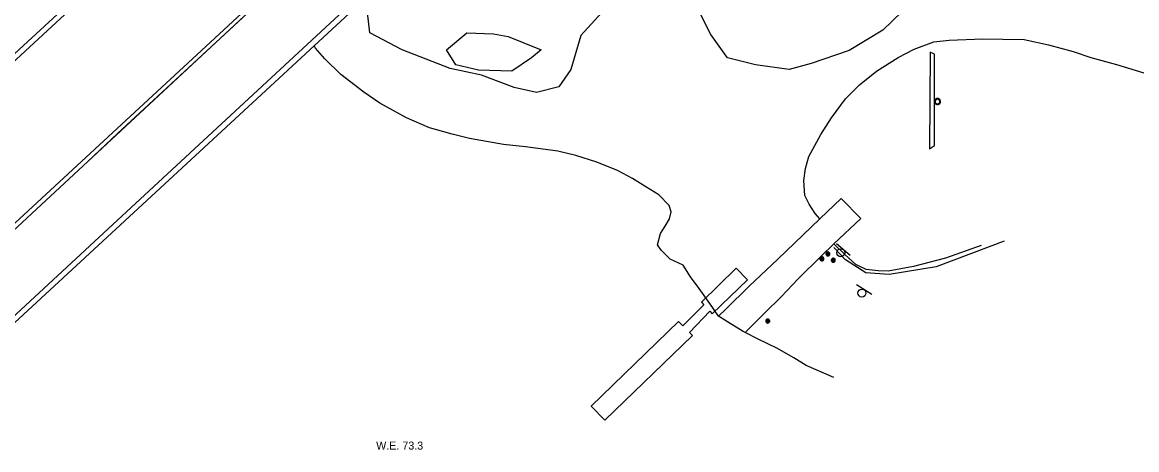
# Model space of a CAD drawing. Extents: x 2161152 to 2175754, y 602179 to 617749.
# Drawn here: x 2171946 to 2172503, y 613312 to 613525 of the extents above; entities that cross this region are included whole.
import ezdxf

# ---------------------------------------------------------------- set-up
doc = ezdxf.new("R2010")
doc.units = 0
for name, color, linetype in [('RD_EX_BldgApp_Deck', 7, 'Continuous'), ('RD_EX_BldgApp_Post', 7, 'Continuous'), ('RD_EX_BldgApp_Sign', 7, 'Continuous'), ('RD_EX_Bridge', 7, 'Continuous'), ('RD_EX_Driveway_Dirt', 7, 'Continuous'), ('RD_EX_Fence_ChLk', 7, 'Continuous'), ('RD_EX_GuardRail', 7, 'Continuous'), ('RD_EX_H2O', 7, 'Continuous'), ('RD_EX_H2O_txCode', 7, 'Continuous'), ('RD_EX_Parking_Conc', 7, 'Continuous'), ('RD_EX_VEG', 7, 'Continuous')]:
    doc.layers.add(name, color=color, linetype=linetype)

msp = doc.modelspace()

# ---------------------------------------------------------------- linework, layer by layer
at = {"layer": 'RD_EX_BldgApp_Deck'}
msp.add_lwpolyline([(2172303.05, 613402.44), (2172285.83, 613385.47), (2172286.98, 613384.23), (2172276.44, 613373.61), (2172274.25, 613375.81), (2172230.7, 613333.61), (2172237.52, 613326.58), (2172281.34, 613368.78), (2172279.79, 613370.3), (2172289.93, 613380.93), (2172291.15, 613379.63), (2172308.71, 613396.66), (2172303.05, 613402.44)], dxfattribs=at)
at = {"layer": 'RD_EX_BldgApp_Post'}
for p, q in [((2172349.54, 613409), (2172348.41, 613410.13)), ((2172348.41, 613409), (2172349.54, 613410.13)), ((2172346.53, 613406.57), (2172345.4, 613407.7)), ((2172345.4, 613406.57), (2172346.53, 613407.7)), ((2172352.23, 613405.84), (2172351.09, 613406.98)), ((2172351.09, 613405.84), (2172352.23, 613406.98)), ((2172319.43, 613375.48), (2172318.3, 613376.62)), ((2172318.3, 613375.48), (2172319.43, 613376.62))]:
    msp.add_line(p, q, dxfattribs=at)
for points in [[(2172349.98, 613409.56), (2172349.96, 613409.72), (2172349.92, 613409.88), (2172349.85, 613410.04), (2172349.75, 613410.2), (2172349.61, 613410.34), (2172349.45, 613410.45), (2172349.26, 613410.52), (2172349.07, 613410.56), (2172348.89, 613410.56), (2172348.72, 613410.53), (2172348.56, 613410.48), (2172348.43, 613410.4), (2172348.3, 613410.31), (2172348.19, 613410.18), (2172348.09, 613410.03), (2172348.01, 613409.85), (2172347.98, 613409.66), (2172347.98, 613409.46), (2172348.01, 613409.27), (2172348.09, 613409.1), (2172348.19, 613408.94), (2172348.3, 613408.82), (2172348.43, 613408.72), (2172348.56, 613408.65), (2172348.72, 613408.59), (2172348.89, 613408.56), (2172349.07, 613408.57), (2172349.26, 613408.6), (2172349.45, 613408.68), (2172349.61, 613408.79), (2172349.75, 613408.93), (2172349.85, 613409.08), (2172349.92, 613409.25), (2172349.96, 613409.41), (2172349.98, 613409.56)], [(2172349.78, 613409.56), (2172349.77, 613409.69), (2172349.73, 613409.82), (2172349.68, 613409.95), (2172349.59, 613410.07), (2172349.48, 613410.18), (2172349.35, 613410.27), (2172349.21, 613410.33), (2172349.05, 613410.36), (2172348.91, 613410.36), (2172348.77, 613410.34), (2172348.65, 613410.29), (2172348.54, 613410.24), (2172348.44, 613410.16), (2172348.34, 613410.06), (2172348.26, 613409.94), (2172348.21, 613409.8), (2172348.18, 613409.64), (2172348.18, 613409.48), (2172348.21, 613409.33), (2172348.26, 613409.19), (2172348.34, 613409.07), (2172348.44, 613408.97), (2172348.54, 613408.89), (2172348.65, 613408.83), (2172348.77, 613408.79), (2172348.91, 613408.76), (2172349.05, 613408.76), (2172349.21, 613408.79), (2172349.35, 613408.86), (2172349.48, 613408.94), (2172349.59, 613409.05), (2172349.68, 613409.18), (2172349.73, 613409.31), (2172349.77, 613409.44), (2172349.78, 613409.56)], [(2172346.96, 613407.14), (2172346.95, 613407.29), (2172346.91, 613407.45), (2172346.84, 613407.62), (2172346.74, 613407.77), (2172346.6, 613407.91), (2172346.43, 613408.02), (2172346.25, 613408.1), (2172346.06, 613408.13), (2172345.88, 613408.14), (2172345.71, 613408.11), (2172345.55, 613408.05), (2172345.42, 613407.98), (2172345.29, 613407.88), (2172345.17, 613407.76), (2172345.08, 613407.6), (2172345, 613407.43), (2172344.96, 613407.24), (2172344.96, 613407.04), (2172345, 613406.85), (2172345.08, 613406.67), (2172345.17, 613406.52), (2172345.29, 613406.39), (2172345.42, 613406.3), (2172345.55, 613406.22), (2172345.71, 613406.17), (2172345.88, 613406.14), (2172346.06, 613406.14), (2172346.25, 613406.18), (2172346.43, 613406.25), (2172346.6, 613406.36), (2172346.74, 613406.5), (2172346.84, 613406.66), (2172346.91, 613406.82), (2172346.95, 613406.98), (2172346.96, 613407.14)], [(2172346.76, 613407.14), (2172346.75, 613407.26), (2172346.72, 613407.39), (2172346.67, 613407.52), (2172346.58, 613407.65), (2172346.47, 613407.76), (2172346.34, 613407.84), (2172346.19, 613407.9), (2172346.04, 613407.94), (2172345.9, 613407.94), (2172345.76, 613407.91), (2172345.63, 613407.87), (2172345.53, 613407.81), (2172345.43, 613407.73), (2172345.33, 613407.63), (2172345.25, 613407.51), (2172345.2, 613407.37), (2172345.16, 613407.22), (2172345.16, 613407.06), (2172345.2, 613406.9), (2172345.25, 613406.76), (2172345.33, 613406.64), (2172345.43, 613406.54), (2172345.53, 613406.46), (2172345.63, 613406.41), (2172345.76, 613406.36), (2172345.9, 613406.34), (2172346.04, 613406.34), (2172346.19, 613406.37), (2172346.34, 613406.43), (2172346.47, 613406.52), (2172346.58, 613406.63), (2172346.67, 613406.75), (2172346.72, 613406.88), (2172346.75, 613407.01), (2172346.76, 613407.14)], [(2172352.66, 613406.41), (2172352.65, 613406.56), (2172352.61, 613406.73), (2172352.54, 613406.89), (2172352.43, 613407.05), (2172352.3, 613407.18), (2172352.13, 613407.29), (2172351.95, 613407.37), (2172351.76, 613407.41), (2172351.58, 613407.41), (2172351.4, 613407.38), (2172351.25, 613407.32), (2172351.12, 613407.25), (2172350.99, 613407.15), (2172350.87, 613407.03), (2172350.77, 613406.88), (2172350.7, 613406.7), (2172350.66, 613406.51), (2172350.66, 613406.31), (2172350.7, 613406.12), (2172350.77, 613405.94), (2172350.87, 613405.79), (2172350.99, 613405.66), (2172351.12, 613405.57), (2172351.25, 613405.49), (2172351.4, 613405.44), (2172351.58, 613405.41), (2172351.76, 613405.41), (2172351.95, 613405.45), (2172352.13, 613405.52), (2172352.3, 613405.63), (2172352.43, 613405.77), (2172352.54, 613405.93), (2172352.61, 613406.09), (2172352.65, 613406.25), (2172352.66, 613406.41)], [(2172352.46, 613406.41), (2172352.45, 613406.53), (2172352.42, 613406.66), (2172352.36, 613406.79), (2172352.28, 613406.92), (2172352.17, 613407.03), (2172352.04, 613407.12), (2172351.89, 613407.18), (2172351.74, 613407.21), (2172351.59, 613407.21), (2172351.46, 613407.18), (2172351.33, 613407.14), (2172351.23, 613407.08), (2172351.12, 613407.01), (2172351.03, 613406.91), (2172350.95, 613406.78), (2172350.89, 613406.64), (2172350.86, 613406.49), (2172350.86, 613406.33), (2172350.89, 613406.18), (2172350.95, 613406.04), (2172351.03, 613405.91), (2172351.12, 613405.81), (2172351.23, 613405.74), (2172351.33, 613405.68), (2172351.46, 613405.63), (2172351.59, 613405.61), (2172351.74, 613405.61), (2172351.89, 613405.64), (2172352.04, 613405.7), (2172352.17, 613405.79), (2172352.28, 613405.9), (2172352.36, 613406.02), (2172352.42, 613406.16), (2172352.45, 613406.29), (2172352.46, 613406.41)], [(2172319.87, 613376.05), (2172319.86, 613376.2), (2172319.82, 613376.37), (2172319.74, 613376.53), (2172319.64, 613376.68), (2172319.5, 613376.82), (2172319.34, 613376.93), (2172319.15, 613377.01), (2172318.97, 613377.05), (2172318.78, 613377.05), (2172318.61, 613377.02), (2172318.45, 613376.96), (2172318.32, 613376.89), (2172318.19, 613376.79), (2172318.08, 613376.67), (2172317.98, 613376.52), (2172317.91, 613376.34), (2172317.87, 613376.15), (2172317.87, 613375.95), (2172317.91, 613375.76), (2172317.98, 613375.58), (2172318.08, 613375.43), (2172318.19, 613375.3), (2172318.32, 613375.21), (2172318.45, 613375.13), (2172318.61, 613375.08), (2172318.78, 613375.05), (2172318.97, 613375.05), (2172319.15, 613375.09), (2172319.34, 613375.16), (2172319.5, 613375.27), (2172319.64, 613375.41), (2172319.74, 613375.57), (2172319.82, 613375.73), (2172319.86, 613375.89), (2172319.87, 613376.05)], [(2172319.67, 613376.05), (2172319.66, 613376.17), (2172319.63, 613376.3), (2172319.57, 613376.43), (2172319.48, 613376.56), (2172319.37, 613376.67), (2172319.24, 613376.76), (2172319.1, 613376.82), (2172318.95, 613376.85), (2172318.8, 613376.85), (2172318.66, 613376.82), (2172318.54, 613376.78), (2172318.43, 613376.72), (2172318.33, 613376.64), (2172318.23, 613376.54), (2172318.16, 613376.42), (2172318.1, 613376.28), (2172318.07, 613376.13), (2172318.07, 613375.97), (2172318.1, 613375.82), (2172318.16, 613375.67), (2172318.23, 613375.55), (2172318.33, 613375.45), (2172318.43, 613375.37), (2172318.54, 613375.32), (2172318.66, 613375.27), (2172318.8, 613375.25), (2172318.95, 613375.25), (2172319.1, 613375.28), (2172319.24, 613375.34), (2172319.37, 613375.43), (2172319.48, 613375.54), (2172319.57, 613375.66), (2172319.63, 613375.79), (2172319.66, 613375.92), (2172319.67, 613376.05)]]:
    msp.add_lwpolyline(points, dxfattribs=at)
at = {"layer": 'RD_EX_BldgApp_Sign'}
for p, q in [((2172360.15, 613408.8), (2172353.24, 613414.56)), ((2172370.83, 613389.25), (2172363.28, 613394.14))]:
    msp.add_line(p, q, dxfattribs=at)
msp.add_lwpolyline([(2172402.31, 613463.68), (2172402.18, 613509.36), (2172400.04, 613510.29), (2172399.7, 613462.03), (2172402.31, 613463.68)], dxfattribs=at)
for centre in [(2172355.39, 613410.13), (2172365.94, 613390.01)]:
    msp.add_circle(centre, 2, dxfattribs=at)
at = {"layer": 'RD_EX_Bridge'}
for points in [[(2171819.91, 613392.88), (2172084.33, 613637.18), (2172083.51, 613638.08), (2172082.76, 613638.9), (2172071.95, 613650.64), (2172061.23, 613662.42), (2172059.85, 613663.94), (2172061.23, 613662.42), (2172071.95, 613650.64), (2172082.76, 613638.9), (2172083.51, 613638.08), (2172084.33, 613637.18), (2171819.91, 613392.88)], [(2171885.06, 613322.4), (2172149.53, 613566.57), (2172148.52, 613567.67), (2172148.24, 613567.98), (2172147.48, 613568.8), (2172137.51, 613579.78), (2172126.99, 613591.08), (2172125.93, 613592.22), (2172124.74, 613593.52), (2171860.26, 613349.01)], [(2171860.26, 613349.01), (2172124.74, 613593.52), (2172125.93, 613592.22), (2172126.99, 613591.08), (2172137.51, 613579.78), (2172147.48, 613568.8), (2172148.24, 613567.98), (2172148.52, 613567.67), (2172149.53, 613566.57), (2171885.06, 613322.4)]]:
    msp.add_lwpolyline(points, dxfattribs=at)
at = {"layer": 'RD_EX_Driveway_Dirt'}
for points in [[(2172344.94, 613427.15), (2172342.64, 613429.75), (2172339.54, 613434.52), (2172337.46, 613438.75), (2172337.01, 613446.18), (2172337.79, 613452.31), (2172339.36, 613458.22), (2172345.39, 613469.19), (2172350.7, 613477.62), (2172357.81, 613487.09), (2172364.7, 613493.97), (2172373.32, 613500.86), (2172384.13, 613507.67), (2172392.15, 613511.82), (2172401.86, 613515.61), (2172409.5, 613516.31), (2172426.42, 613517.06), (2172436.32, 613516.86), (2172447.05, 613516.65), (2172459.19, 613513.97), (2172471.58, 613510.76), (2172480.35, 613507.63), (2172493.13, 613504.13), (2172506.78, 613500.11)], [(2172425.53, 613413.78), (2172407.74, 613407.47), (2172391.77, 613403.36), (2172379.04, 613401), (2172374.02, 613401.14), (2172368.02, 613401.78), (2172362.98, 613404.22), (2172357.66, 613409.09), (2172351.97, 613414.66)]]:
    msp.add_lwpolyline(points, dxfattribs=at)
at = {"layer": 'RD_EX_Fence_ChLk'}
msp.add_lwpolyline([(2172437.1, 613415.92), (2172403.1, 613403.2), (2172379.63, 613399.28), (2172367.89, 613400.15), (2172357.67, 613406.55), (2172351.9, 613412.73)], dxfattribs=at)
at = {"layer": 'RD_EX_GuardRail'}
for points in [[(2172147.48, 613568.8), (2172000.82, 613432.78), (2171883.46, 613324.27), (2172000.82, 613432.78), (2172147.48, 613568.8), (2172155.2, 613576.14), (2172195.7, 613608.45), (2172213.09, 613622.4), (2172232.29, 613638.65), (2172275.32, 613675.64), (2172303.3, 613699.46), (2172337.27, 613727.47), (2172371.63, 613755.39), (2172429.34, 613801.67), (2172473.43, 613837.02), (2172503.28, 613860.99)], [(2172082.76, 613638.9), (2171925.39, 613494)], [(2171925.39, 613494), (2172082.76, 613638.9)], [(2172141.49, 613606.49), (2171993.96, 613469.72), (2171979.13, 613455.67), (2172125.94, 613592.22), (2171979.13, 613455.67), (2171861.98, 613347.22)]]:
    msp.add_lwpolyline(points, dxfattribs=at)
at = {"layer": 'RD_EX_H2O'}
for points in [[(2172351.93, 613347.91), (2172338.14, 613353.85), (2172332.01, 613357.66), (2172323.37, 613362.49), (2172314.06, 613366.94), (2172307.55, 613370.3), (2172306.6, 613370.8), (2172298.77, 613375.6), (2172294.33, 613378.41), (2172289.89, 613384.83), (2172284.68, 613392.34), (2172280.35, 613398.09), (2172276.55, 613403.95), (2172270.19, 613406.9), (2172265.61, 613411.39), (2172263.77, 613414.18), (2172265.36, 613419.79), (2172267.69, 613423.51), (2172269.75, 613427.11), (2172270.6, 613430.61), (2172269.64, 613433.84), (2172264.49, 613439.08), (2172258.04, 613443.1), (2172251.38, 613447.33), (2172243.86, 613451.25), (2172233.47, 613455.34), (2172222.93, 613458.77), (2172213.94, 613460.94), (2172197.89, 613463.09), (2172186.87, 613464.27), (2172169.85, 613467.19), (2172161.26, 613469.35), (2172149.85, 613472.6), (2172138.29, 613477.53), (2172124.95, 613484.92), (2172116.95, 613490.46), (2172105.52, 613499.24), (2172097.6, 613507.04), (2172092.92, 613512.34), (2172092.23, 613513.66)], [(2172404.14, 613487.18), (2172403.34, 613487.19), (2172402.64, 613486.78), (2172402.24, 613486.09), (2172402.24, 613485.29), (2172402.64, 613484.59), (2172403.34, 613484.19), (2172404.14, 613484.19), (2172404.84, 613484.59), (2172405.24, 613485.28), (2172405.24, 613486.09), (2172404.84, 613486.78), (2172404.14, 613487.18)], [(2172404.9, 613485.69), (2172404.89, 613485.86), (2172404.85, 613486.05), (2172404.76, 613486.24), (2172404.64, 613486.42), (2172404.48, 613486.58), (2172404.29, 613486.71), (2172404.08, 613486.8), (2172403.86, 613486.84), (2172403.64, 613486.85), (2172403.44, 613486.81), (2172403.26, 613486.75), (2172403.11, 613486.66), (2172402.96, 613486.55), (2172402.83, 613486.41), (2172402.71, 613486.23), (2172402.63, 613486.02), (2172402.58, 613485.8), (2172402.58, 613485.57), (2172402.63, 613485.35), (2172402.71, 613485.14), (2172402.83, 613484.96), (2172402.96, 613484.82), (2172403.11, 613484.71), (2172403.26, 613484.62), (2172403.44, 613484.56), (2172403.64, 613484.52), (2172403.86, 613484.53), (2172404.08, 613484.57), (2172404.29, 613484.66), (2172404.48, 613484.79), (2172404.64, 613484.95), (2172404.76, 613485.13), (2172404.85, 613485.32), (2172404.89, 613485.51), (2172404.9, 613485.69)]]:
    msp.add_lwpolyline(points, dxfattribs=at)
at = {"layer": 'RD_EX_Parking_Conc'}
msp.add_lwpolyline([(2172294.33, 613378.41), (2172298.02, 613381.92), (2172309.64, 613393.41), (2172323.92, 613407), (2172344.94, 613427.15), (2172355.54, 613437.23), (2172365.44, 613427.31), (2172351.97, 613414.66), (2172345.53, 613408.39), (2172334.09, 613397.07), (2172325.53, 613388.18), (2172317.5, 613380.1), (2172309.54, 613372.28), (2172307.55, 613370.3)], dxfattribs=at)
at = {"layer": 'RD_EX_VEG'}
for points in [[(2172236.04, 613530.12), (2172225.54, 613518.77), (2172220.43, 613501.64), (2172214.54, 613493.06), (2172203.26, 613490.25), (2172192.17, 613492.76), (2172175.88, 613498.91), (2172160.16, 613502.24), (2172136.26, 613511.47), (2172120.06, 613520.01), (2172118.81, 613530.16)], [(2172385.84, 613530.55), (2172376.48, 613521.3), (2172359.65, 613511.24), (2172340.53, 613504.71), (2172329.52, 613501.63), (2172312.84, 613504.07), (2172298.86, 613507.48), (2172290.48, 613519.2), (2172284.74, 613530.31)], [(2172205.73, 613511.56), (2172200.8, 613507.47), (2172190.99, 613500.88), (2172174.37, 613501.32), (2172163.02, 613504.11), (2172158.35, 613511.59), (2172168.48, 613520.02), (2172181.77, 613519.56), (2172189.18, 613518.24), (2172205.73, 613511.56)]]:
    msp.add_lwpolyline(points, dxfattribs=at)

# ---------------------------------------------------------------- texts
at = {"layer": 'RD_EX_H2O_txCode'}
msp.add_text('W.E. 73.3', height=4, dxfattribs=at).set_placement((2172123.21, 613311.84))

doc.saveas('drawing.dxf')
